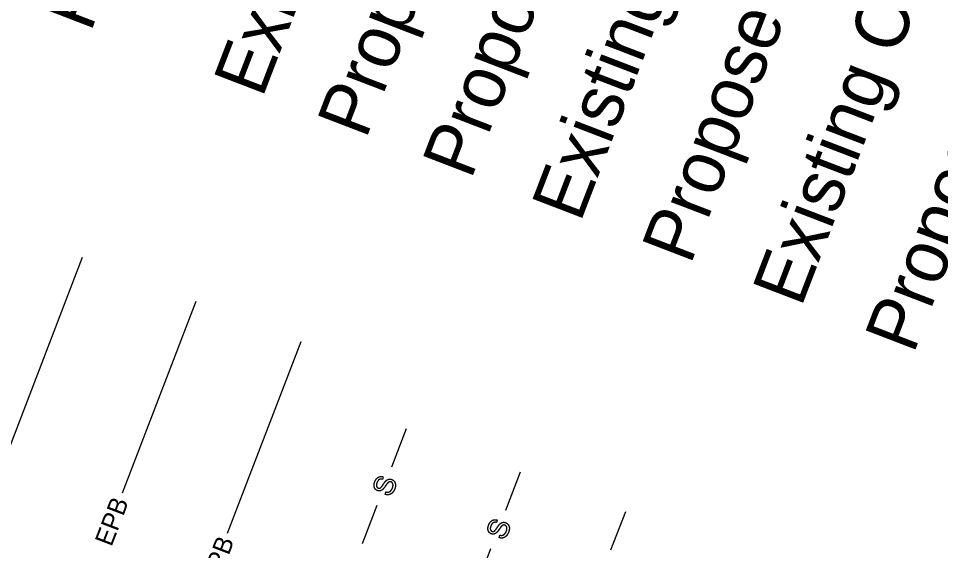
# Model space of a CAD drawing. Extents: x 1015221 to 1064345, y 619216 to 647967.
# Drawn here: x 1047582 to 1048770, y 627103 to 627789 of the extents above; entities that cross this region are included whole.
import ezdxf

# ---------------------------------------------------------------- set-up
doc = ezdxf.new("R2010")
doc.units = 0
doc.layers.add('Default', color=7, linetype='Continuous')

msp = doc.modelspace()

# ---------------------------------------------------------------- linework, layer by layer
at = {"layer": 'Default'}
for p, q in [((1047570.6, 627235.5), (1047664.9, 627481.2)), ((1047716.4, 627177.6), (1047811.4, 627424.9)), ((1047851.7, 627125.6), (1047946.7, 627372.9)), ((1048063.4, 627211.1), (1048082.3, 627260.4)), ((1048210.1, 627155.4), (1048229, 627204.7)), ((1048052.3, 627198.3), (1048051.3, 627195.1)), ((1048054.8, 627175.7), (1048055.7, 627178.9)), ((1048025.5, 627112.4), (1048044.4, 627161.8)), ((1048345.7, 627104.3), (1048364.7, 627153.6)), ((1048199, 627142.7), (1048198, 627139.5)), ((1048201.5, 627120), (1048202.4, 627123.2)), ((1048172.2, 627056.8), (1048191.1, 627106.1))]:
    msp.add_line(p, q, dxfattribs=at)
for points in [[(1048040.4, 627187), (1048040.4, 627189.4), (1048041.3, 627191.9)], [(1048041.3, 627191.9), (1048042.4, 627194.6), (1048044.1, 627196.4)], [(1048044.3, 627190.9), (1048043.1, 627187.9), (1048043.7, 627186.2)], [(1048044.1, 627196.4), (1048045.8, 627198.1), (1048047.9, 627198.6)], [(1048047.1, 627194.8), (1048045.4, 627193.8), (1048044.3, 627190.9)], [(1048051.3, 627195.1), (1048048.9, 627195.8), (1048047.1, 627194.8)], [(1048047.9, 627198.6), (1048050.1, 627199.1), (1048052.3, 627198.3)], [(1048052, 627188.2), (1048054.4, 627191.8), (1048055.7, 627193.1)], [(1048055.7, 627193.1), (1048057.5, 627194.8), (1048059.4, 627195.3)], [(1048060.1, 627191.8), (1048059, 627191.5), (1048057.8, 627190.1)], [(1048059.4, 627195.3), (1048061.3, 627195.7), (1048063.3, 627194.9)], [(1048062.4, 627191.7), (1048061.2, 627192.1), (1048060.1, 627191.8)], [(1048064.2, 627190.2), (1048063.5, 627191.3), (1048062.4, 627191.7)], [(1048063.3, 627194.9), (1048065.3, 627194.2), (1048066.6, 627192.4)], [(1048066.6, 627192.4), (1048067.9, 627190.6), (1048068.1, 627188.1)], [(1048041.7, 627183), (1048040.5, 627184.7), (1048040.4, 627187)], [(1048044.8, 627180.6), (1048042.9, 627181.3), (1048041.7, 627183)], [(1048043.7, 627186.2), (1048044.3, 627184.4), (1048045.8, 627183.8)], [(1048048.2, 627180.3), (1048046.5, 627179.9), (1048044.8, 627180.6)], [(1048045.8, 627183.8), (1048047.1, 627183.3), (1048048.3, 627183.9)], [(1048051.5, 627182), (1048049.9, 627180.6), (1048048.2, 627180.3)], [(1048048.3, 627183.9), (1048049.6, 627184.5), (1048052, 627188.2)], [(1048054.9, 627186.2), (1048052.8, 627183.1), (1048051.5, 627182)], [(1048057.8, 627190.1), (1048057, 627189.3), (1048054.9, 627186.2)], [(1048055.7, 627178.9), (1048057.7, 627178.4), (1048059.2, 627178.7)], [(1048059.2, 627178.7), (1048060.7, 627179), (1048062, 627180.4)], [(1048062, 627180.4), (1048063.4, 627181.9), (1048064.2, 627184)], [(1048067.2, 627183), (1048065.9, 627179.6), (1048064.1, 627177.7)], [(1048064.9, 627187.5), (1048064.9, 627189.1), (1048064.2, 627190.2)], [(1048064.2, 627184), (1048064.9, 627185.8), (1048064.9, 627187.5)], [(1048068.1, 627188.1), (1048068.2, 627185.6), (1048067.2, 627183)], [(1048059.8, 627175.3), (1048057.3, 627174.8), (1048054.8, 627175.7)], [(1048064.1, 627177.7), (1048062.2, 627175.9), (1048059.8, 627175.3)], [(1048187.2, 627131.4), (1048187.1, 627133.7), (1048188.1, 627136.2)], [(1048188.4, 627127.3), (1048187.2, 627129), (1048187.2, 627131.4)], [(1048188.1, 627136.2), (1048189.1, 627139), (1048190.8, 627140.7)], [(1048191, 627135.2), (1048189.8, 627132.3), (1048190.4, 627130.5)], [(1048190.8, 627140.7), (1048192.5, 627142.5), (1048194.6, 627142.9)], [(1048193.8, 627139.1), (1048192.1, 627138.1), (1048191, 627135.2)], [(1048198, 627139.5), (1048195.6, 627140.1), (1048193.8, 627139.1)], [(1048194.6, 627142.9), (1048196.8, 627143.4), (1048199, 627142.7)], [(1048195.1, 627128.2), (1048196.3, 627128.9), (1048198.7, 627132.5)], [(1048198.7, 627132.5), (1048201.2, 627136.2), (1048202.4, 627137.4)], [(1048204.5, 627134.5), (1048203.7, 627133.6), (1048201.6, 627130.5)], [(1048202.4, 627137.4), (1048204.2, 627139.1), (1048206.1, 627139.6)], [(1048206.8, 627136.1), (1048205.7, 627135.8), (1048204.5, 627134.5)], [(1048206.1, 627139.6), (1048208, 627140), (1048210, 627139.3)], [(1048209.1, 627136), (1048207.9, 627136.5), (1048206.8, 627136.1)], [(1048210.9, 627134.5), (1048210.2, 627135.6), (1048209.1, 627136)], [(1048210, 627139.3), (1048212, 627138.5), (1048213.3, 627136.7)], [(1048211.7, 627131.8), (1048211.6, 627133.4), (1048210.9, 627134.5)], [(1048210.9, 627128.3), (1048211.7, 627130.2), (1048211.7, 627131.8)], [(1048213.3, 627136.7), (1048214.6, 627134.9), (1048214.8, 627132.4)], [(1048214.8, 627132.4), (1048214.9, 627130), (1048213.9, 627127.3)], [(1048191.5, 627124.9), (1048189.7, 627125.6), (1048188.4, 627127.3)], [(1048190.4, 627130.5), (1048191, 627128.7), (1048192.5, 627128.1)], [(1048194.9, 627124.6), (1048193.2, 627124.2), (1048191.5, 627124.9)], [(1048192.5, 627128.1), (1048193.8, 627127.6), (1048195.1, 627128.2)], [(1048198.2, 627126.3), (1048196.6, 627124.9), (1048194.9, 627124.6)], [(1048201.6, 627130.5), (1048199.5, 627127.4), (1048198.2, 627126.3)], [(1048206.5, 627119.6), (1048204, 627119.1), (1048201.5, 627120)], [(1048202.4, 627123.2), (1048204.4, 627122.7), (1048205.9, 627123)], [(1048205.9, 627123), (1048207.4, 627123.4), (1048208.8, 627124.8)], [(1048210.8, 627122.1), (1048208.9, 627120.2), (1048206.5, 627119.6)], [(1048208.8, 627124.8), (1048210.1, 627126.2), (1048210.9, 627128.3)], [(1048213.9, 627127.3), (1048212.6, 627124), (1048210.8, 627122.1)]]:
    msp.add_open_spline(points, degree=2, dxfattribs=at)

# ---------------------------------------------------------------- texts
for s, height, p in [('Proposed Permanent Easement Monument', 68.654, (1047675.2, 627770)), ('Proposed C/A Monument (Rebar and Cap)', 68.654, (1048029.8, 627632.2)), ('Proposed C/A Monument (Concrete)', 68.654, (1048165.3, 627580.1)), ('Proposed Control of Access Line', 68.654, (1048735.4, 627355.4)), ('Existing Control of Access Line', 68.654, (1048590.6, 627415.6)), ('Existing C/A Monument', 68.654, (1047896.3, 627685.3)), ('Proposed Right of Way Line', 68.654, (1048448, 627470.4)), ('Existing Right of Way Line', 68.654, (1048306.1, 627524.9)), ('EPB', 23.54, (1047702.1, 627107.5)), ('HPB', 23.54, (1047837.4, 627055.5))]:
    msp.add_text(s, height=height, rotation=68.983, dxfattribs=at).set_placement(p)

doc.saveas('drawing.dxf')
